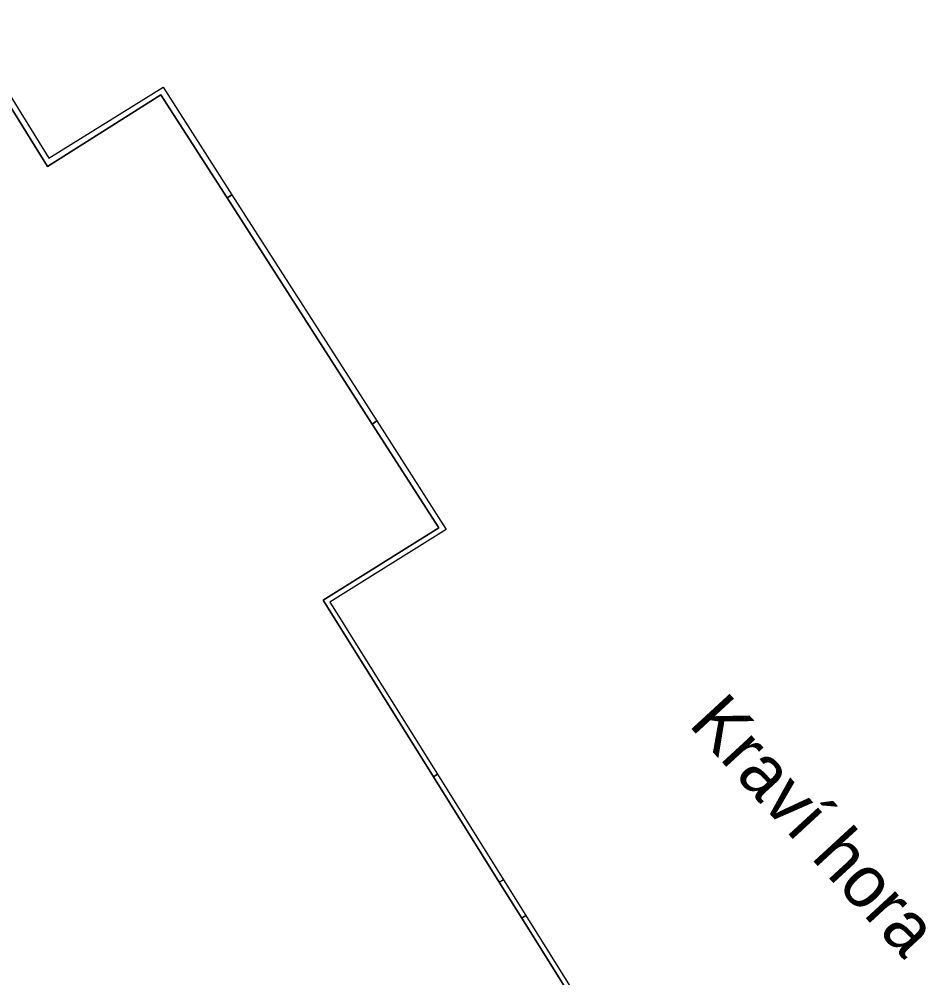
# Model space of a CAD drawing. Extents: x -600391 to -599491, y -1160176 to -1159402.
# Drawn here: x -599808.86 to -599773.91, y -1159510.41 to -1159473.45 of the extents above; entities that cross this region are included whole.
import ezdxf

# ---------------------------------------------------------------- set-up
doc = ezdxf.new("R2010")
doc.units = 0
for name, color, linetype in [('Level 11', 7, 'Continuous'), ('Level 61', 7, 'Continuous'), ('Level 62', 7, 'Continuous')]:
    doc.layers.add(name, color=color, linetype=linetype)

msp = doc.modelspace()

# ---------------------------------------------------------------- linework, layer by layer
at = {"layer": 'Level 61'}
for points in [[(-599807.77, -1159479.12), (-599814.19, -1159468.75)], [(-599814.19, -1159468.75), (-599807.77, -1159479.12)], [(-599811, -1159473.5), (-599807.71, -1159478.8)], [(-599807.71, -1159478.8), (-599803.31, -1159476.07)], [(-599803.31, -1159476.07), (-599800.66, -1159480.22)], [(-599803.39, -1159476.36), (-599807.77, -1159479.12)], [(-599807.77, -1159479.12), (-599803.39, -1159476.36)], [(-599800.84, -1159480.34), (-599803.39, -1159476.36)], [(-599803.39, -1159476.36), (-599800.84, -1159480.34)], [(-599800.66, -1159480.22), (-599800.84, -1159480.34)], [(-599800.84, -1159480.34), (-599800.66, -1159480.22)], [(-599800.84, -1159480.34), (-599795.25, -1159489.06)], [(-599795.25, -1159489.06), (-599800.84, -1159480.34)], [(-599800.66, -1159480.22), (-599795.07, -1159488.94)], [(-599795.25, -1159489.06), (-599795.07, -1159488.94)], [(-599795.07, -1159488.94), (-599795.25, -1159489.06)], [(-599792.68, -1159493.06), (-599795.25, -1159489.06)], [(-599795.25, -1159489.06), (-599792.68, -1159493.06)], [(-599795.07, -1159488.94), (-599792.39, -1159493.13)], [(-599797.14, -1159495.85), (-599792.68, -1159493.06)], [(-599792.68, -1159493.06), (-599797.14, -1159495.85)], [(-599792.39, -1159493.13), (-599796.88, -1159495.92)], [(-599792.89, -1159502.66), (-599797.14, -1159495.85)], [(-599797.14, -1159495.85), (-599792.89, -1159502.66)], [(-599796.88, -1159495.92), (-599796.55, -1159496.45)], [(-599796.55, -1159496.45), (-599795.85, -1159497.57)], [(-599795.85, -1159497.57), (-599792.89, -1159502.31)], [(-599792.89, -1159502.31), (-599792.73, -1159502.56)], [(-599792.73, -1159502.56), (-599792.89, -1159502.66)], [(-599792.89, -1159502.66), (-599792.73, -1159502.56)], [(-599792.89, -1159502.66), (-599790.35, -1159506.72)], [(-599790.35, -1159506.72), (-599792.89, -1159502.66)], [(-599792.73, -1159502.56), (-599790.19, -1159506.63)], [(-599790.35, -1159506.72), (-599790.19, -1159506.63)], [(-599790.19, -1159506.63), (-599790.35, -1159506.72)], [(-599790.35, -1159506.72), (-599789.48, -1159508.11)], [(-599789.48, -1159508.11), (-599790.35, -1159506.72)], [(-599790.19, -1159506.63), (-599789.33, -1159508.01)], [(-599789.48, -1159508.11), (-599789.33, -1159508.01)], [(-599789.33, -1159508.01), (-599789.48, -1159508.11)], [(-599789.33, -1159508.01), (-599782.69, -1159518.64)], [(-599789.48, -1159508.11), (-599782.84, -1159518.74)], [(-599782.84, -1159518.74), (-599789.48, -1159508.11)]]:
    msp.add_lwpolyline(points, dxfattribs=at)
at = {"layer": 'Level 62'}
for points in [[(-599811.76, -1159472.28), (-599811, -1159473.5), (-599807.71, -1159478.8), (-599803.31, -1159476.07), (-599800.66, -1159480.22), (-599800.84, -1159480.34), (-599803.39, -1159476.36), (-599807.77, -1159479.12), (-599814.19, -1159468.75), (-599814.56, -1159468.98), (-599814.68, -1159468.79), (-599814.12, -1159468.47), (-599811.76, -1159472.28)], [(-599809.71, -1159511.1), (-599813.06, -1159505.79), (-599817.46, -1159508.59), (-599819.96, -1159504.61), (-599824.4, -1159497.59), (-599825.07, -1159496.53), (-599825.53, -1159495.81), (-599828.07, -1159491.79), (-599823.57, -1159489.01), (-599830.05, -1159478.65), (-599829.66, -1159478.41), (-599814.56, -1159468.98), (-599814.19, -1159468.75), (-599807.77, -1159479.12), (-599803.39, -1159476.36), (-599800.84, -1159480.34), (-599795.25, -1159489.06), (-599792.68, -1159493.06), (-599797.14, -1159495.85), (-599792.89, -1159502.66), (-599790.35, -1159506.72), (-599789.48, -1159508.11), (-599782.84, -1159518.74)], [(-599795.07, -1159488.94), (-599795.25, -1159489.06), (-599800.84, -1159480.34), (-599800.66, -1159480.22), (-599795.07, -1159488.94)], [(-599795.07, -1159488.94), (-599792.39, -1159493.13), (-599796.88, -1159495.92), (-599796.55, -1159496.45), (-599795.85, -1159497.57), (-599792.89, -1159502.31), (-599792.73, -1159502.56), (-599792.89, -1159502.66), (-599797.14, -1159495.85), (-599792.68, -1159493.06), (-599795.25, -1159489.06), (-599795.07, -1159488.94)], [(-599792.89, -1159502.66), (-599792.73, -1159502.56), (-599790.19, -1159506.63), (-599790.35, -1159506.72), (-599792.89, -1159502.66)], [(-599789.48, -1159508.11), (-599790.35, -1159506.72), (-599790.19, -1159506.63), (-599789.33, -1159508.01), (-599789.48, -1159508.11)], [(-599789.48, -1159508.11), (-599789.33, -1159508.01), (-599782.69, -1159518.64), (-599782.84, -1159518.74), (-599789.48, -1159508.11)]]:
    msp.add_lwpolyline(points, dxfattribs=at)

# ---------------------------------------------------------------- texts
at = {"layer": 'Level 11'}
msp.add_text('Kraví hora', height=2, rotation=312.6471, dxfattribs=at).set_placement((-599783.091, -1159500.654))

doc.saveas('drawing.dxf')
